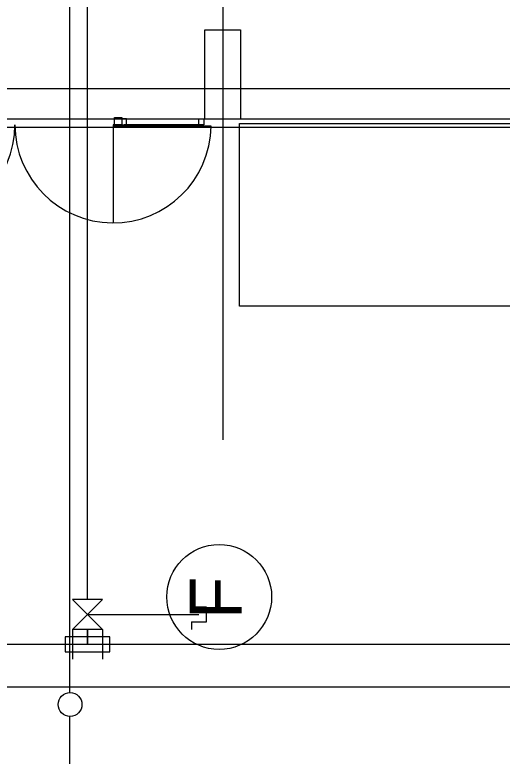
# Model space of a CAD drawing. Extents: x -264222 to -263592, y -1242345 to -1242048.
# Drawn here: x -263887.96 to -263879.77, y -1242252.15 to -1242239.56 of the extents above; entities that cross this region are included whole.
import ezdxf

# ---------------------------------------------------------------- set-up
doc = ezdxf.new("R2010")
doc.units = 0
for name, color, linetype in [('HESCON_OSI_STAVBY_KFA', 7, 'Continuous'), ('KFA_2D_SITUACIA_DSP', 7, 'Continuous'), ('KFA_SO_62-1_VO_TRASA_KABLOV_PROJEKT', 7, 'Continuous')]:
    doc.layers.add(name, color=color, linetype=linetype)

msp = doc.modelspace()

# ---------------------------------------------------------------- linework, layer by layer
at = {"layer": 'HESCON_OSI_STAVBY_KFA'}
for p, q in [((-263884.468, -1242083.237), (-263884.468, -1242246.707)), ((-263792.653, -1242240.807), (-263911.523, -1242240.807))]:
    msp.add_line(p, q, dxfattribs=at)
msp.add_circle((-263884.528, -1242249.345), 0.882, dxfattribs=at)
at = {"layer": 'KFA_2D_SITUACIA_DSP'}
for p, q in [((-263887.043, -1242235.757), (-263887.043, -1242250.954)), ((-263886.743, -1242249.39), (-263886.743, -1242235.757)), ((-263884.768, -1242241.312), (-263884.768, -1242239.812)), ((-263884.768, -1242239.812), (-263884.168, -1242239.812)), ((-263884.168, -1242239.812), (-263884.168, -1242241.312)), ((-263894.581, -1242241.307), (-263809.355, -1242241.307)), ((-263886.288, -1242241.407), (-263886.288, -1242241.287)), ((-263886.288, -1242241.287), (-263886.168, -1242241.287)), ((-263886.168, -1242241.287), (-263886.168, -1242241.407)), ((-263886.088, -1242241.307), (-263886.168, -1242241.307)), ((-263886.168, -1242241.307), (-263886.168, -1242241.407)), ((-263886.088, -1242241.407), (-263886.088, -1242241.307)), ((-263884.868, -1242241.407), (-263884.868, -1242241.307)), ((-263884.868, -1242241.307), (-263884.788, -1242241.307)), ((-263884.788, -1242241.307), (-263884.788, -1242241.407)), ((-263884.168, -1242241.312), (-263884.768, -1242241.312)), ((-263884.188, -1242244.458), (-263884.188, -1242241.388)), ((-263884.188, -1242241.388), (-263876.738, -1242241.388)), ((-263886.288, -1242241.407), (-263886.313, -1242241.407)), ((-263886.313, -1242241.407), (-263886.313, -1242243.057)), ((-263884.663, -1242241.432), (-263886.313, -1242241.432)), ((-263886.168, -1242241.407), (-263886.288, -1242241.407)), ((-263886.168, -1242241.407), (-263886.128, -1242241.407)), ((-263884.828, -1242241.407), (-263886.128, -1242241.407)), ((-263886.128, -1242241.407), (-263886.128, -1242241.432)), ((-263886.128, -1242241.407), (-263886.088, -1242241.407)), ((-263886.128, -1242241.432), (-263884.828, -1242241.432)), ((-263884.828, -1242241.407), (-263884.868, -1242241.407)), ((-263884.828, -1242241.432), (-263884.828, -1242241.407)), ((-263884.788, -1242241.407), (-263884.828, -1242241.407)), ((-263876.738, -1242244.458), (-263884.188, -1242244.458)), ((-263886.493, -1242249.39), (-263886.993, -1242249.39)), ((-263886.993, -1242249.89), (-263886.493, -1242249.39)), ((-263886.993, -1242249.39), (-263886.493, -1242249.89)), ((-263884.993, -1242249.515), (-263884.993, -1242249.39)), ((-263884.743, -1242249.515), (-263884.993, -1242249.515)), ((-263884.743, -1242249.765), (-263884.743, -1242249.515)), ((-263886.743, -1242249.64), (-263884.868, -1242249.64)), ((-263884.993, -1242249.765), (-263884.993, -1242249.89)), ((-263884.993, -1242249.765), (-263884.743, -1242249.765)), ((-263886.493, -1242249.89), (-263886.993, -1242249.89)), ((-263886.993, -1242249.89), (-263886.993, -1242250.39)), ((-263886.743, -1242250.14), (-263886.743, -1242249.89)), ((-263886.743, -1242249.89), (-263886.743, -1242250.14)), ((-263886.493, -1242249.89), (-263886.493, -1242250.39)), ((-263886.368, -1242250.015), (-263887.118, -1242250.015)), ((-263887.118, -1242250.015), (-263887.118, -1242250.265)), ((-263886.368, -1242250.265), (-263886.368, -1242250.015)), ((-263924.143, -1242250.14), (-263788.143, -1242250.14)), ((-263887.118, -1242250.265), (-263886.368, -1242250.265)), ((-263887.043, -1242251.353), (-263887.043, -1242252.153))]:
    msp.add_line(p, q, dxfattribs=at)
msp.add_lwpolyline([(-263794.893, -1242227.382), (-263808.968, -1242241.457), (-263894.968, -1242241.457), (-263909.043, -1242227.382), (-263909.043, -1242196.333), (-263914.143, -1242196.333), (-263914.143, -1242132.433), (-263909.043, -1242132.433), (-263909.043, -1242101.382), (-263894.968, -1242087.307), (-263808.968, -1242087.307), (-263794.893, -1242101.382), (-263794.893, -1242227.382)], dxfattribs=at)
msp.add_circle((-263887.036, -1242251.153), 0.2, dxfattribs=at)
for centre, start, end in [((-263889.613, -1242241.407), 180.8682, 0), ((-263886.313, -1242241.407), 180, 359.1318)]:
    msp.add_arc(centre, 1.65, start, end, dxfattribs=at)
at = {"layer": 'KFA_SO_62-1_VO_TRASA_KABLOV_PROJEKT'}
msp.add_line((-263876.338, -1242250.863), (-263895.338, -1242250.863), dxfattribs=at)

# ---------------------------------------------------------------- texts
at = {"layer": 'HESCON_OSI_STAVBY_KFA'}
msp.add_text('F', height=0.875, rotation=90, dxfattribs=at).set_placement((-263884.147, -1242249.718))

doc.saveas('drawing.dxf')
